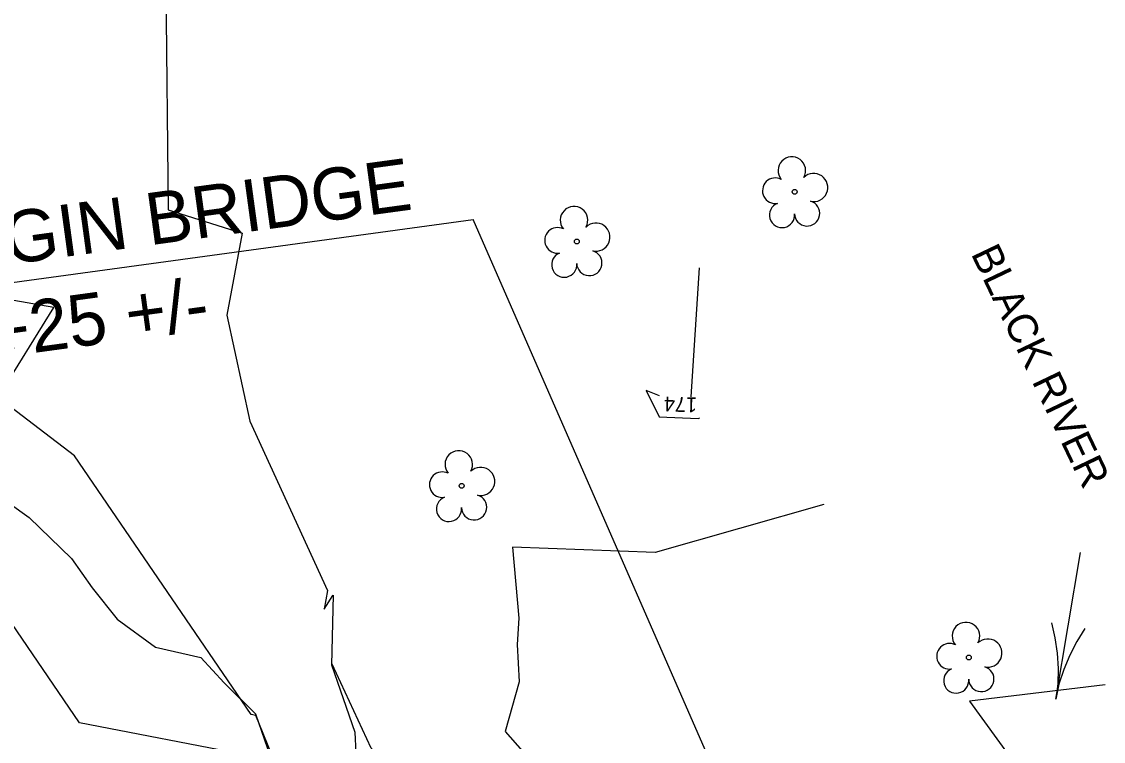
# Model space of a CAD drawing. Extents: x 2086416 to 2115205, y 575507 to 632762.
# Drawn here: x 2111920.5 to 2112066, y 581788.1 to 581885 of the extents above; entities that cross this region are included whole.
import ezdxf

# ---------------------------------------------------------------- set-up
doc = ezdxf.new("R2010")
doc.units = 0
for name, color, linetype in [('DTM Contours Minor', 7, 'Continuous'), ('DTM Contours Minor Text', 7, 'Continuous'), ('Exist Hydro River Flow Arrow CELL', 7, 'Continuous'), ('Exist Hydro Stream or Body of Water', 7, 'Continuous'), ('Exist Hydro Stream or Body of Water Text', 7, 'Continuous'), ('Exist Vegetation Tree CELL', 7, 'Continuous'), ('Prop Horizontal Alignment Station Label', 7, 'Continuous')]:
    doc.layers.add(name, color=color, linetype=linetype)

# ---------------------------------------------------------------- blocks, each defined once
blk = doc.blocks.new('EXIST VEGETATION TREE')
at = {"layer": 'Exist Vegetation Tree CELL'}
blk.add_line((0, 0), (0, 0), dxfattribs=at)
blk.add_circle((0, 0), 0.00652, dxfattribs=at)
for centre, radius, start, end in [((-0.0077, 0.0575), 0.0371, 330.1651, 219.7134), ((-0.0521, 0.0031), 0.0345, 62.6636, 279.3457), ((0.051, 0.0118), 0.038, 257.1011, 134.1999), ((0.0335, -0.058), 0.034, 181.2822, 74.56), ((-0.0341, -0.0624), 0.0338, 111.5671, 6.231)]:
    blk.add_arc(centre, radius, start, end, dxfattribs=at)

msp = doc.modelspace()

# ---------------------------------------------------------------- linework, layer by layer
at = {"layer": 'DTM Contours Minor'}
for points in [[(2111986.57, 581903.53), (2111939.89, 581889.69), (2111940.22, 581859.65), (2111950.16, 581856.54), (2111948.11, 581845.47), (2111951.21, 581831.21), (2111961.67, 581808.41), (2111961.19, 581805.94), (2111962.39, 581807.77), (2111962.43, 581807.8), (2111962.19, 581798.43), (2111965.32, 581789.35), (2111965.47, 581786.59), (2111973.88, 581778.03), (2111977.11, 581774.63), (2111980.39, 581770.88), (2111987.46, 581769.35), (2111990.76, 581766.29)], [(2112011.63, 581851.85), (2112010.53, 581834.49)], [(2111965.16, 581748.51), (2111970.69, 581749.86), (2111976.47, 581749.51), (2111981.91, 581752.5), (2111983.32, 581753.31), (2111982.36, 581755.79), (2111980.14, 581760.97), (2111975.64, 581761.52), (2111969.46, 581763.24), (2111967.22, 581769.18), (2111966.98, 581769.81), (2111965.9, 581771.13), (2111955.64, 581782.68), (2111952.51, 581790.39), (2111952, 581791.62), (2111951.36, 581791.75), (2111927.6, 581826.56), (2111917.31, 581834.4), (2111924.82, 581846.5), (2111912.24, 581848.72), (2111889.78, 581833.71), (2111886.95, 581833.16), (2111879.3, 581820.3)], [(2112006.32, 581834.62), (2112004.52, 581835.36), (2112006.26, 581831.8), (2112011.5, 581831.6), (2112011.73, 581831.66)], [(2112028.44, 581819.99), (2112005.74, 581813.55), (2111986.52, 581814.28), (2111987.37, 581804.69), (2111987.18, 581801.17), (2111987.42, 581796.12), (2111985.53, 581789.47), (2111990.87, 581783.42)], [(2111872.65, 581745.71), (2111876.29, 581746.03), (2111892.64, 581747.28), (2111896.68, 581747.18), (2111903.16, 581748.2), (2111906.44, 581747.76), (2111910.2, 581745.85), (2111927.92, 581748.91), (2111939.7, 581750.88), (2111951.09, 581752.85), (2111957.32, 581753.9), (2111972.19, 581756.27), (2111962.31, 581758.92), (2111961.55, 581761.08), (2111960.4, 581763.71), (2111955.81, 581769.32), (2111952.04, 581783.78), (2111951.03, 581786.21), (2111928.27, 581790.63), (2111917.03, 581807.1), (2111909.85, 581812.57), (2111903.37, 581811.31)], [(2112066.28, 581795.74), (2112048, 581793.55), (2112061.06, 581775.54), (2112061.72, 581774.65), (2112054.08, 581764.55), (2112060.15, 581764.51), (2112053.46, 581749.4), (2112053.37, 581746.7), (2112053.2, 581742.71), (2112053.57, 581738.55), (2112056.36, 581729.73), (2112057.47, 581723.04), (2112058.24, 581720.01), (2112063.98, 581709.95), (2112064.08, 581709.79), (2112064.18, 581709.63), (2112064.52, 581708.58), (2112068.43, 581698.96)]]:
    msp.add_lwpolyline(points, dxfattribs=at)
at = {"layer": 'Exist Hydro River Flow Arrow CELL'}
for p, q in [((2112059.64, 581793.82), (2112062.93, 581813.55)), ((2112059.03, 581804.06), (2112059.49, 581802.07)), ((2112061.28, 581803.68), (2112061.28, 581803.68)), ((2112063.54, 581803.31), (2112062.45, 581801.57)), ((2112059.49, 581802.07), (2112059.8, 581800.01)), ((2112062.45, 581801.57), (2112061.5, 581799.73)), ((2112059.8, 581800.01), (2112059.93, 581797.93)), ((2112061.5, 581799.73), (2112060.7, 581797.8)), ((2112059.93, 581797.93), (2112059.9, 581795.85)), ((2112060.7, 581797.8), (2112060.05, 581795.83)), ((2112059.9, 581795.85), (2112059.64, 581793.82)), ((2112060.05, 581795.83), (2112059.64, 581793.82))]:
    msp.add_line(p, q, dxfattribs=at)
at = {"layer": 'Exist Hydro Stream or Body of Water'}
for points in [[(2111914.05, 581823.59), (2111921.52, 581818.26), (2111927.21, 581812.76), (2111929.98, 581808.81), (2111933.37, 581804.58), (2111938.52, 581800.81), (2111944.63, 581799.41), (2111947.75, 581796), (2111952.02, 581791.78)], [(2112059.94, 581700.98), (2112062.59, 581707.22), (2112055.44, 581716.4), (2112054.67, 581722.41), (2112052.26, 581739.2), (2112051.84, 581739.05), (2112049.8, 581742.56), (2112050.11, 581752.77), (2112039.24, 581754.19), (2112006.97, 581748.92), (2112002.42, 581748.72), (2111999.87, 581752.29), (2111991.63, 581772.37), (2111979.18, 581775.68), (2111967.53, 581787.22), (2111962.27, 581798.52)], [(2111979.59, 581759.49), (2111969.33, 581762.97), (2111966.87, 581769.78), (2111955.26, 581782.47), (2111952.02, 581791.78)]]:
    msp.add_lwpolyline(points, dxfattribs=at)
at = {"layer": 'Prop Horizontal Alignment Station Label'}
for p in [(2111851.3, 581840.64), (2112041.04, 581721.6)]:
    msp.add_line(p, (2111981.25, 581858.37), dxfattribs=at)

# ---------------------------------------------------------------- block references
at = {"layer": 'Exist Vegetation Tree CELL', "xscale": 50, "yscale": 50}
for p in [(2112024.5, 581862.08), (2111995.2, 581855.4), (2111979.7, 581822.52), (2112047.93, 581799.42)]:
    msp.add_blockref('EXIST VEGETATION TREE', p, dxfattribs=at)

# ---------------------------------------------------------------- texts
at = {"layer": 'DTM Contours Minor Text'}
msp.add_text('174', height=2, rotation=178.2142, dxfattribs=at).set_placement((2112011.4, 581834.4))
at = {"layer": 'Exist Hydro Stream or Body of Water Text'}
msp.add_text('BLACK RIVER', height=4, rotation=295.5556, dxfattribs=at).set_placement((2112048.15, 581853.78))
at = {"layer": 'Prop Horizontal Alignment Station Label'}
for s, p in [('BEGIN BRIDGE', (2111906.26, 581850.59)), (' -L- POT Sta. 19+25 +/-  ', (2111849.09, 581830.43))]:
    msp.add_text(s, height=7, rotation=7.771, dxfattribs=at).set_placement(p)

doc.saveas('drawing.dxf')
